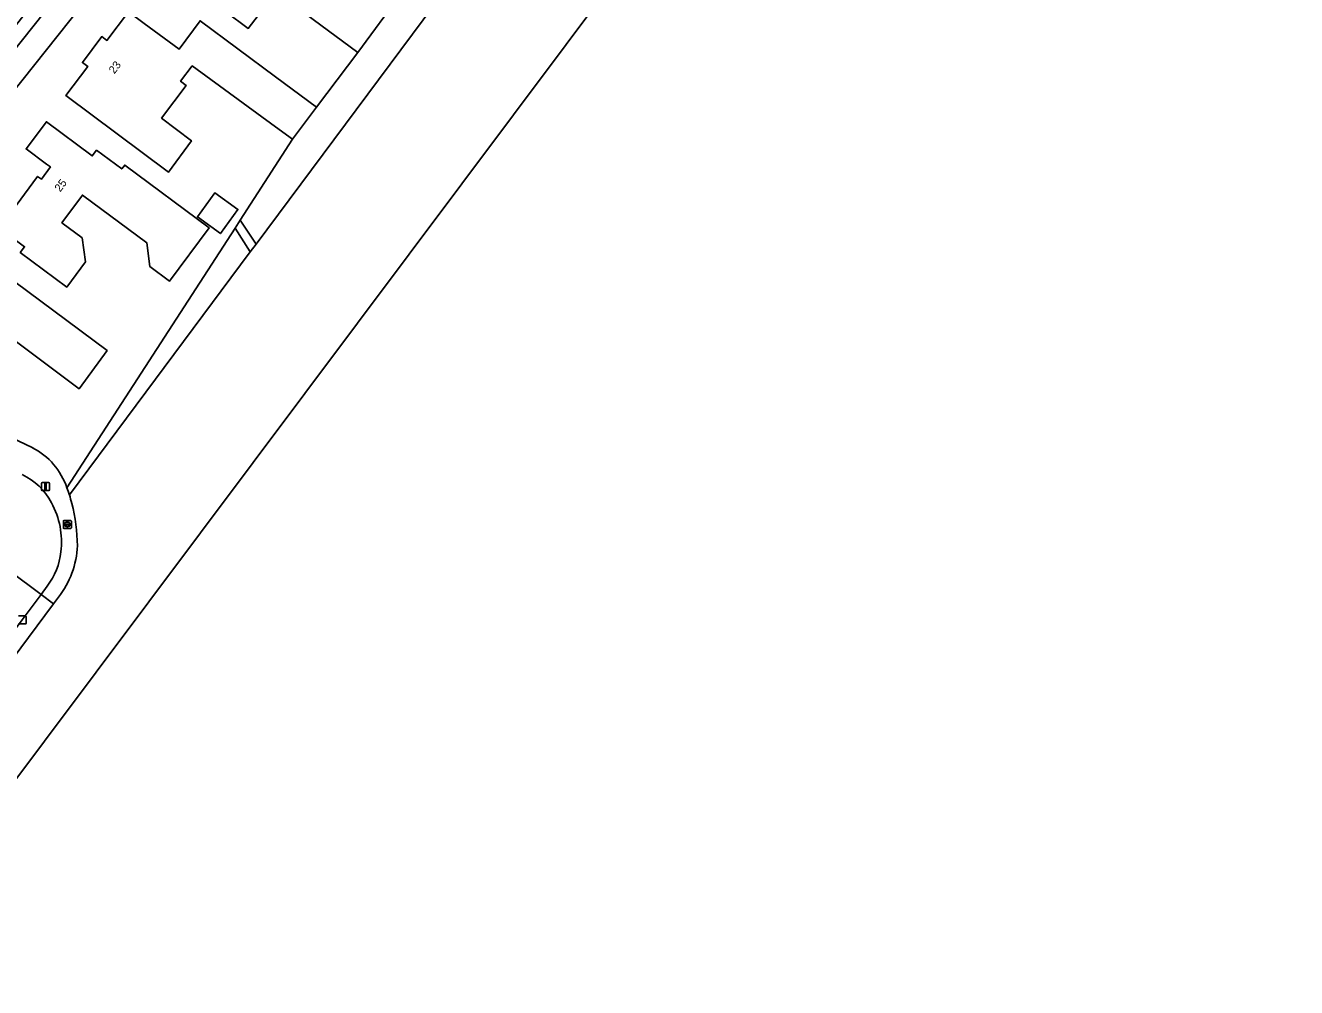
# Model space of a CAD drawing. Extents: x 158835 to 160077, y 386387 to 387778.
# Drawn here: x 159468.8 to 159627.5, y 386515.3 to 386635.5 of the extents above; entities that cross this region are included whole.
import ezdxf

# ---------------------------------------------------------------- set-up
doc = ezdxf.new("R2010")
doc.units = 0
for name, color, linetype in [('IMGEO_Erf', 7, 'Continuous'), ('IMGEO_Grasland_agrarisch', 7, 'Continuous'), ('IMGEO_Groenvoorziening', 7, 'Continuous'), ('IMGEO_Kolk', 7, 'Continuous'), ('IMGEO_Lichtmast', 7, 'Continuous'), ('IMGEO_Pand', 7, 'Continuous'), ('IMGEO_Pand_nummerreeks', 7, 'Continuous'), ('IMGEO_Parkeervlak_open', 7, 'Continuous'), ('IMGEO_Rijbaan_lokaal_open', 7, 'Continuous'), ('IMGEO_Rioolput', 7, 'Continuous'), ('IMGEO_Voetpad_open', 7, 'Continuous')]:
    doc.layers.add(name, color=color, linetype=linetype)

msp = doc.modelspace()

# ---------------------------------------------------------------- linework, layer by layer
at = {"layer": 'IMGEO_Erf'}
for points in [[(159480.3, 386643.69), (159466.86, 386626.71)], [(159483.62, 386635.72), (159487.98, 386632.52), (159490.58, 386636.07), (159500, 386629.08), (159505.12, 386625.27), (159510.29, 386632.12), (159500.07, 386639.68), (159496.61, 386635.11), (159493.81, 386637.18)], [(159473.96, 386577.73), (159494.96, 386610.16), (159495.59, 386611.14), (159502.14, 386621.26), (159500, 386622.82), (159489.61, 386630.43), (159488.15, 386628.5), (159488.85, 386627.97), (159485.78, 386623.9), (159489.51, 386621.07), (159486.63, 386617.14), (159473.82, 386626.72), (159476.55, 386630.37), (159475.9, 386630.85), (159478.3, 386634.08), (159478.95, 386633.6), (159481.63, 386637.18)], [(159443.3, 386595.38), (159451.53, 386591.43), (159451.49, 386591.3), (159466.99, 386584), (159469.68, 386582.73)]]:
    msp.add_lwpolyline(points, dxfattribs=at)
for points in [[(159477.12, 386619.19), (159477.65, 386619.9), (159480.81, 386617.56), (159481.17, 386618.04), (159491.73, 386610.18), (159486.77, 386603.54), (159484.32, 386605.36), (159483.92, 386608.34), (159475.88, 386614.29), (159473.32, 386610.83), (159475.87, 386608.95), (159476.29, 386605.97), (159473.94, 386602.79), (159468.12, 386607.12), (159468.66, 386607.83), (159465.49, 386610.17), (159470.29, 386616.62), (159470.76, 386616.27), (159471.9, 386617.8), (159471.41, 386618.14), (159468.86, 386620.06), (159471.39, 386623.46)], [(159495.32, 386612.51), (159493.13, 386609.49), (159490.26, 386611.56), (159492.45, 386614.59)], [(159463.98, 386606), (159478.98, 386594.86), (159475.48, 386590.11), (159466.64, 386596.69), (159463.76, 386592.81), (159461.6, 386594.46), (159461.32, 386594.08), (159460.31, 386594.85), (159458.52, 386592.44), (159457.9, 386591.61), (159454.48, 386594.15), (159453.8, 386593.27), (159449.72, 386596.32), (159454.61, 386602.92), (159455, 386603.45), (159456.04, 386602.67), (159457.83, 386605.1), (159457.34, 386605.46), (159457.72, 386605.97), (159459.98, 386608.99)]]:
    msp.add_lwpolyline(points, close=True, dxfattribs=at)
msp.add_arc((159465.47, 386574.8), 8.98, 19.0886, 62.0743, dxfattribs=at)
at = {"layer": 'IMGEO_Grasland_agrarisch'}
for points in [[(159472.89, 386564.06), (159472.29, 386563.25), (159446.53, 386528.63), (159445.6, 386527.38), (159441.92, 386522.39), (159446.75, 386525.57), (159464.54, 386537.3), (159608.05, 386728.94), (159627.55, 386754.97)], [(159627.55, 386754.97), (159626.26, 386754.64), (159608.28, 386750), (159603.12, 386748.67), (159599.84, 386747.83), (159600.16, 386746.98), (159599.24, 386744.73), (159497.58, 386608.17), (159496.86, 386607.2), (159474.26, 386576.85)]]:
    msp.add_lwpolyline(points, dxfattribs=at)
for centre, radius, start, end in [((159457.07, 386571.34), 18.05, 14.2258, 17.7639), ((159453.39, 386570.28), 21.87, 0.572, 14.5461), ((159464.1, 386570.95), 11.17, 321.8663, 357.67)]:
    msp.add_arc(centre, radius, start, end, dxfattribs=at)
at = {"layer": 'IMGEO_Groenvoorziening'}
msp.add_lwpolyline([(159599.24, 386744.73), (159600.16, 386746.98), (159599.84, 386747.83), (159595.41, 386746.69), (159591.3, 386741.16), (159576.15, 386720.78), (159563.63, 386703.91), (159558.06, 386696.44), (159540.93, 386673.4), (159533.39, 386663.27), (159529, 386657.37), (159526.45, 386653.92), (159515.73, 386639.55), (159510.29, 386632.12), (159505.12, 386625.27), (159502.14, 386621.26), (159495.59, 386611.14), (159497.58, 386608.17)], close=True, dxfattribs=at)
for points in [[(159496.86, 386607.2), (159494.96, 386610.16), (159473.96, 386577.73)], [(159474.26, 386576.85), (159496.86, 386607.2)]]:
    msp.add_lwpolyline(points, dxfattribs=at)
msp.add_arc((159454.84, 386570.77), 20.34, 17.3887, 20.0235, dxfattribs=at)
at = {"layer": 'IMGEO_Kolk'}
for p, q in [((159467.92, 386561.72), (159468.77, 386561.72)), ((159468.77, 386560.72), (159467.92, 386560.72)), ((159468.85, 386561.64), (159468.85, 386560.79))]:
    msp.add_line(p, q, dxfattribs=at)
for points in [[(159467.92, 386561.72), (159468.77, 386561.72)], [(159468.77, 386560.72), (159467.92, 386560.72)], [(159468.85, 386561.64), (159468.85, 386560.79)]]:
    msp.add_lwpolyline(points, dxfattribs=at)
for centre, start, end in [((159468.77, 386561.64), 1.552, 88.448), ((159468.77, 386561.64), 1.552, 88.448), ((159468.77, 386560.79), 271.552, 358.448), ((159468.77, 386560.79), 271.552, 358.448)]:
    msp.add_arc(centre, 0.0765, start, end, dxfattribs=at)
at = {"layer": 'IMGEO_Lichtmast'}
for p, q in [((159470.78, 386577.48), (159470.78, 386578.28)), ((159470.78, 386578.28), (159470.78, 386577.48)), ((159470.88, 386578.38), (159471.67, 386578.38)), ((159471.67, 386578.38), (159470.88, 386578.38)), ((159471.77, 386578.28), (159471.77, 386577.48)), ((159471.77, 386577.48), (159471.77, 386578.28)), ((159471.67, 386577.38), (159470.88, 386577.38)), ((159470.88, 386577.38), (159471.67, 386577.38))]:
    msp.add_line(p, q, dxfattribs=at)
msp.add_lwpolyline([(159471.2, 386578.25), (159471.35, 386578.25), (159471.35, 386577.5), (159471.2, 386577.5), (159471.2, 386578.25)], dxfattribs=at)
for centre, start, end in [((159470.88, 386578.28), 90, 180), ((159470.88, 386578.28), 90, 180), ((159471.67, 386578.28), 0, 90), ((159471.67, 386578.28), 360, 90), ((159470.88, 386577.48), 180, 270), ((159470.88, 386577.48), 180, 270), ((159471.67, 386577.48), 270, 0), ((159471.67, 386577.48), 270, 0)]:
    msp.add_arc(centre, 0.1, start, end, dxfattribs=at)
at = {"layer": 'IMGEO_Pand'}
for points in [[(159505.57, 386647.75), (159503.8, 386645.37), (159502.97, 386645.99), (159504.01, 386647.39), (159500, 386650.37), (159497.48, 386652.25), (159495.49, 386649.61), (159494.61, 386650.27), (159492.5, 386651.81), (159492.11, 386651.29), (159489.99, 386648.44), (159485.96, 386642.99), (159489.7, 386640.23), (159493.81, 386637.18), (159496.61, 386635.11), (159500.07, 386639.68), (159510.29, 386632.12), (159515.73, 386639.55), (159513.71, 386641.05), (159514.04, 386641.48)], [(159505.12, 386625.27), (159500, 386629.08), (159490.58, 386636.07), (159487.98, 386632.52), (159483.62, 386635.72), (159481.63, 386637.18), (159478.95, 386633.6), (159478.3, 386634.08), (159475.9, 386630.85), (159476.55, 386630.37), (159473.82, 386626.72), (159486.63, 386617.14), (159489.51, 386621.07), (159485.78, 386623.9), (159488.85, 386627.97), (159488.15, 386628.5), (159489.61, 386630.43), (159500, 386622.82), (159502.14, 386621.26)], [(159465.49, 386610.17), (159468.66, 386607.83), (159468.12, 386607.12), (159473.94, 386602.79), (159476.29, 386605.97), (159475.87, 386608.95), (159473.32, 386610.83), (159475.88, 386614.29), (159483.92, 386608.34), (159484.32, 386605.36), (159486.77, 386603.54), (159491.73, 386610.18), (159481.17, 386618.04), (159480.81, 386617.56), (159477.65, 386619.9), (159477.12, 386619.19), (159471.39, 386623.46), (159468.86, 386620.06), (159471.41, 386618.14), (159471.9, 386617.8), (159470.76, 386616.27), (159470.29, 386616.62)], [(159492.45, 386614.59), (159490.26, 386611.56), (159493.13, 386609.49), (159495.32, 386612.51)], [(159458.52, 386592.44), (159460.31, 386594.85), (159461.32, 386594.08), (159461.6, 386594.46), (159463.76, 386592.81), (159466.64, 386596.69), (159475.48, 386590.11), (159478.98, 386594.86), (159463.98, 386606), (159459.98, 386608.99), (159457.72, 386605.97), (159457.34, 386605.46), (159457.83, 386605.1), (159456.04, 386602.67), (159455, 386603.45), (159454.61, 386602.92), (159449.72, 386596.32), (159453.8, 386593.27), (159454.48, 386594.15), (159457.9, 386591.61)]]:
    msp.add_lwpolyline(points, close=True, dxfattribs=at)
at = {"layer": 'IMGEO_Parkeervlak_open'}
msp.add_lwpolyline([(159475.35, 386642.47), (159473.92, 386643.59), (159465.7, 386633.1), (159462.67, 386629.43), (159464.07, 386628.28), (159464.15, 386628.38)], close=True, dxfattribs=at)
at = {"layer": 'IMGEO_Rijbaan_lokaal_open'}
for points in [[(159458.52, 386547.99), (159468.35, 386561.22), (159470.73, 386564.41), (159466.78, 386567.35), (159464.49, 386564.35), (159454.73, 386551.24), (159443.03, 386535.52), (159432.24, 386521.01), (159431.06, 386519.46), (159430.98, 386519.31), (159430.47, 386518.75), (159429.9, 386518.26)], [(159466.95, 386567.54), (159466.78, 386567.35), (159470.73, 386564.41), (159471.5, 386565.45)]]:
    msp.add_lwpolyline(points, dxfattribs=at)
for centre, radius, start, end in [((159465.02, 386572.21), 7.9, 27.5721, 65.0165), ((159463.1, 386570.95), 10.18, 353.0923, 28.8373), ((159464.66, 386570.67), 8.6, 322.617, 353.7295)]:
    msp.add_arc(centre, radius, start, end, dxfattribs=at)
at = {"layer": 'IMGEO_Rioolput'}
for p, q in [((159473.51, 386572.72), (159473.51, 386573.58)), ((159473.58, 386573.65), (159474.43, 386573.65)), ((159474, 386573.43), (159474.02, 386573.43)), ((159474.51, 386573.58), (159474.51, 386572.72)), ((159474.43, 386572.65), (159473.58, 386572.65)), ((159473.77, 386573.14), (159473.77, 386573.16)), ((159473.81, 386573.19), (159474.21, 386573.19)), ((159474.2, 386573.11), (159473.81, 386573.11)), ((159474.02, 386572.87), (159473.99, 386572.87)), ((159474.25, 386573.16), (159474.25, 386573.14))]:
    msp.add_line(p, q, dxfattribs=at)
for points in [[(159473.51, 386572.72), (159473.51, 386573.58)], [(159473.58, 386573.65), (159474.43, 386573.65)], [(159474.51, 386573.58), (159474.51, 386572.72)], [(159474.43, 386572.65), (159473.58, 386572.65)]]:
    msp.add_lwpolyline(points, dxfattribs=at)
for centre, radius, start, end in [((159473.58, 386573.57), 0.0765, 91.552, 178.448), ((159473.58, 386573.57), 0.0765, 91.552, 178.448), ((159474.43, 386573.57), 0.0765, 1.552, 88.448), ((159474.43, 386573.57), 0.0765, 1.552, 88.448), ((159473.58, 386572.73), 0.0765, 181.552, 268.448), ((159473.58, 386572.73), 0.0765, 181.552, 268.448), ((159473.81, 386573.15), 0.0403, 85.8775, 175.7526), ((159473.8, 386573.14), 0.0366, 178.938, 274.7102), ((159474.21, 386573.15), 0.043, 264.8664, 352.4533), ((159474.21, 386573.15), 0.0386, 1.7309, 96.639), ((159474.43, 386572.73), 0.0765, 271.552, 358.448), ((159474.43, 386572.73), 0.0765, 271.552, 358.448)]:
    msp.add_arc(centre, radius, start, end, dxfattribs=at)
for centre, major_axis, ratio, start_param, end_param in [((159473.99, 386573.15), (-0.387, 0.002), 0.722429, 4.712389, 7.853982), ((159474.02, 386573.15), (-0.39, 0.002), 0.717154, 1.570796, 4.712389)]:
    msp.add_ellipse(centre, major_axis=major_axis, ratio=ratio, start_param=start_param, end_param=end_param, dxfattribs=at)
at = {"layer": 'IMGEO_Voetpad_open'}
for points in [[(159452.92, 386610.02), (159466.86, 386626.71), (159480.3, 386643.69), (159492.02, 386659.9), (159492.43, 386660.37), (159500, 386671.53), (159500.25, 386671.91), (159506.85, 386682.05), (159520.83, 386705.1), (159521.9, 386707.47), (159522.76, 386709.92), (159523.4, 386712.44), (159523.81, 386715.01), (159523.99, 386717.61), (159523.94, 386720.21), (159523.83, 386721.44), (159523.61, 386726.84), (159524.85, 386728.53), (159523.61, 386733.3), (159523.38, 386733.24)], [(159475.35, 386642.47), (159464.15, 386628.38)], [(159469.68, 386582.73), (159466.99, 386584), (159451.49, 386591.3), (159451.53, 386591.43), (159443.3, 386595.38)], [(159471.5, 386565.45), (159470.73, 386564.41), (159472.29, 386563.25), (159472.89, 386564.06)], [(159441.92, 386522.39), (159445.6, 386527.38), (159446.53, 386528.63), (159472.29, 386563.25), (159470.73, 386564.41), (159468.35, 386561.22), (159458.52, 386547.99), (159446.9, 386532.34), (159435.88, 386517.53), (159435.72, 386517.32), (159435.19, 386516.59), (159434.97, 386516.3), (159434.23, 386515.3)]]:
    msp.add_lwpolyline(points, dxfattribs=at)
msp.add_lwpolyline([(159495.59, 386611.14), (159494.96, 386610.16), (159496.86, 386607.2), (159497.58, 386608.17)], close=True, dxfattribs=at)
for centre, radius, start, end in [((159465.47, 386574.8), 8.98, 19.0886, 62.0743), ((159465.02, 386572.21), 7.9, 27.5721, 65.0165), ((159454.84, 386570.77), 20.34, 17.3887, 20.0235), ((159457.07, 386571.34), 18.05, 14.2258, 17.7639), ((159463.1, 386570.95), 10.18, 353.0923, 28.8373), ((159453.39, 386570.28), 21.87, 0.572, 14.5461), ((159464.1, 386570.95), 11.17, 321.8663, 357.67), ((159464.66, 386570.67), 8.6, 322.617, 353.7295)]:
    msp.add_arc(centre, radius, start, end, dxfattribs=at)

# ---------------------------------------------------------------- texts
at = {"layer": 'IMGEO_Pand_nummerreeks'}
for s, rotation, p in [('23', 53.3239, (159479.89, 386629.36)), ('25', 53.4371, (159473.12, 386614.62))]:
    msp.add_text(s, height=1, rotation=rotation, dxfattribs=at).set_placement(p)

doc.saveas('drawing.dxf')
